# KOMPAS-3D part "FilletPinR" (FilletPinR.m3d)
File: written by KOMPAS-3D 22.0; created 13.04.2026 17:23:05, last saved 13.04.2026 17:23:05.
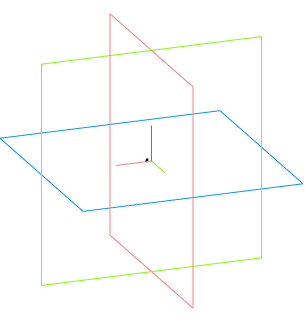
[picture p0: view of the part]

Document properties: Автор: Andrey; Полное имя файла: C:\Users\User1\Documents\FilletPinR.m3d

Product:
- Part/product: FilletPinR

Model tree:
1. Операция без истории:1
